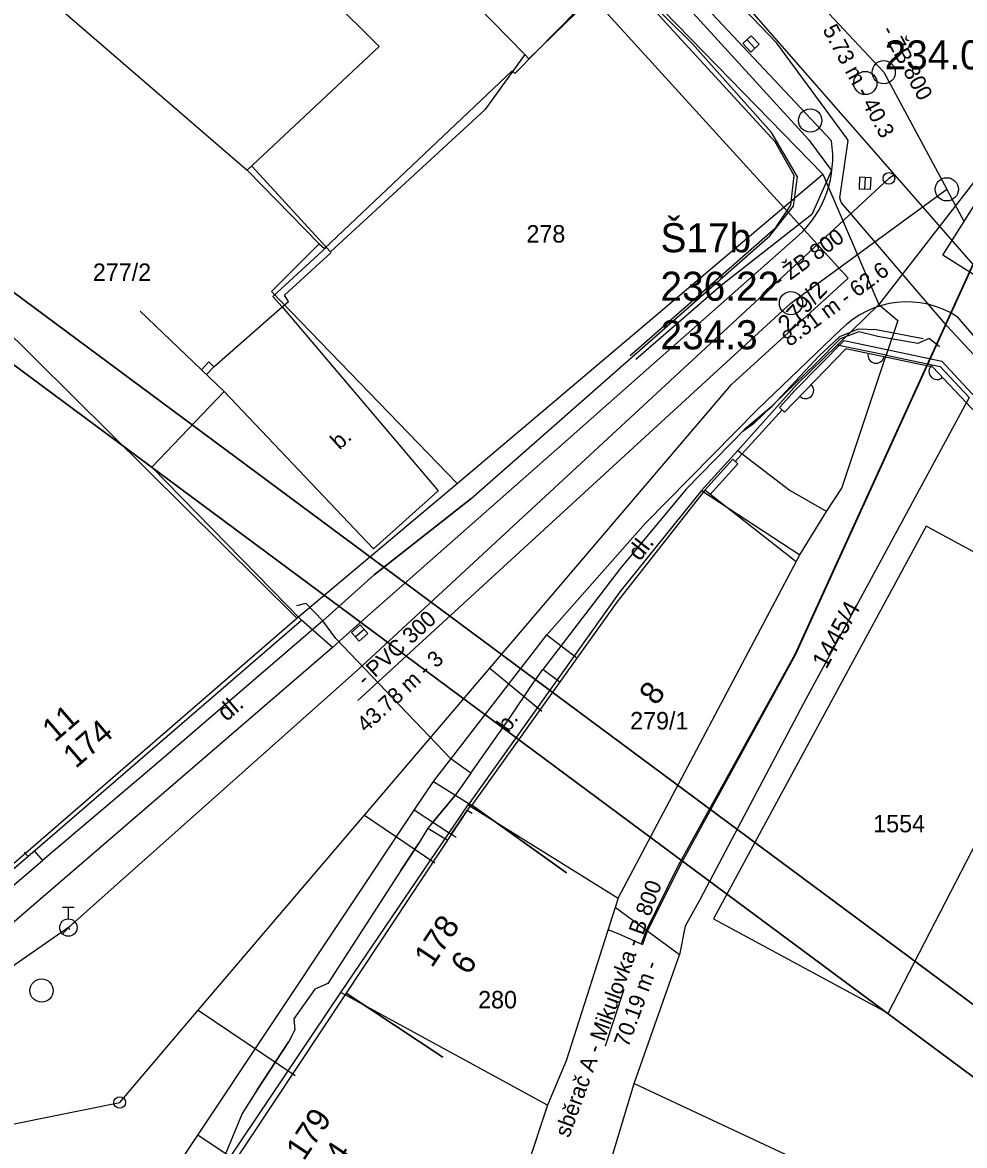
# Model space of a CAD drawing. Extents: x -601580 to 4, y -1204314 to 4.
# Drawn here: x -600436.29 to -600395.73, y -1203947.55 to -1203899.19 of the extents above; entities that cross this region are included whole.
import ezdxf

# ---------------------------------------------------------------- set-up
doc = ezdxf.new("R2010")
doc.units = 0
for name, color, linetype in [('00-EON NN', 7, 'Continuous'), ('00-EON VN', 7, 'Continuous'), ('00-INNOGY-NTL', 7, 'Continuous'), ('00-INNOGY-STL', 7, 'Continuous'), ('00-KN-HRANICE PARCEL', 7, 'Continuous'), ('00-KN-PARC. CISLA', 7, 'Continuous'), ('00-KN-VNITRNI KRESBA', 7, 'Continuous'), ('00-POLOHOPIS', 7, 'Continuous'), ('00-RAZÍTKO', 7, 'Continuous'), ('00-SITE KOM. KABEL', 7, 'Continuous'), ('00-VAK-KANAL-ODLEHCOVACI KOMORA', 7, 'Continuous'), ('00-VAK-KANAL-POPIS', 7, 'Continuous'), ('00-VAK-KANAL-POTRUBI', 7, 'Continuous'), ('00-VAK-VODA-RAD IGIS', 7, 'Continuous'), ('Vrstva 27', 7, 'Continuous'), ('Vrstva 28', 7, 'Continuous'), ('Vrstva 40', 7, 'Continuous'), ('Vrstva 6', 7, 'Continuous')]:
    doc.layers.add(name, color=color, linetype=linetype)

# ---------------------------------------------------------------- blocks, each defined once
blk = doc.blocks.new('6.14A_864')
at = {"layer": 'Vrstva 28'}
blk.add_circle((0, 0), 0.25, dxfattribs=at)
blk = doc.blocks.new('6.13_280')
at = {"layer": 'Vrstva 28'}
for p, q in [((-0.25, 0.875), (0.25, 0.875)), ((0, 0.375), (0, 0.875)), ((-0.258, -0.272), (0.272, 0.258))]:
    blk.add_line(p, q, dxfattribs=at)
blk.add_circle((0, 0), 0.375, dxfattribs=at)
blk = doc.blocks.new('6.30_278')
at = {"layer": 'Vrstva 27'}
blk.add_line((-0.25, 0), (0.25, 0), dxfattribs=at)
blk.add_lwpolyline([(-0.25, -0.249), (0.249, -0.25), (0.25, 0.249), (-0.249, 0.25)], close=True, dxfattribs=at)
blk = doc.blocks.new('6.20_204')
at = {"layer": 'Vrstva 27'}
blk.add_circle((0, 0), 0.5, dxfattribs=at)
blk = doc.blocks.new('6.20_206')
at = {"layer": 'Vrstva 27'}
blk.add_circle((0, 0), 0.5, dxfattribs=at)
blk = doc.blocks.new('6.20_208')
at = {"layer": 'Vrstva 27'}
blk.add_circle((0, 0), 0.5, dxfattribs=at)
blk = doc.blocks.new('6.30_282')
at = {"layer": 'Vrstva 27'}
blk.add_line((-0.25, 0), (0.25, 0), dxfattribs=at)
blk.add_lwpolyline([(-0.25, -0.25), (0.25, -0.25), (0.25, 0.25), (-0.25, 0.25)], close=True, dxfattribs=at)
blk = doc.blocks.new('6.30_284')
at = {"layer": 'Vrstva 27'}
blk.add_line((-0.25, 0.001), (0.25, -0.001), dxfattribs=at)
blk.add_lwpolyline([(-0.25, -0.25), (0.25, -0.25), (0.25, 0.25), (-0.25, 0.25)], close=True, dxfattribs=at)
blk = doc.blocks.new('6.20_210')
at = {"layer": 'Vrstva 27'}
blk.add_circle((0, 0), 0.5, dxfattribs=at)
blk = doc.blocks.new('6.14A_1010')
at = {"layer": 'Vrstva 28'}
blk.add_circle((0, 0), 0.25, dxfattribs=at)
blk = doc.blocks.new('DL_52')
at = {"layer": 'Vrstva 40'}
blk.add_text('dl.', height=0.75, rotation=0, dxfattribs=at).set_placement((-0.174, -0.376))
blk = doc.blocks.new('DL_54')
at = {"layer": 'Vrstva 40'}
blk.add_text('dl.', height=0.75, rotation=0, dxfattribs=at).set_placement((-0.174, -0.375))
blk = doc.blocks.new('VCHOD_1788')
at = {"layer": 'Vrstva 6'}
blk.add_line((0, 0.25), (0, 0), dxfattribs=at)
blk = doc.blocks.new('VCHOD_1790')
at = {"layer": 'Vrstva 6'}
blk.add_line((0, 0.25), (0, 0), dxfattribs=at)
blk = doc.blocks.new('VCHOD_1806')
at = {"layer": 'Vrstva 6'}
blk.add_line((0, 0.25), (0, 0), dxfattribs=at)

msp = doc.modelspace()

# ---------------------------------------------------------------- linework, layer by layer
for points in [[(-600427.929, -1203789.586), (-600429.936, -1203788.096), (-600492.548, -1203872.448), (-600373.307, -1203960.957), (-600310.695, -1203876.605), (-600312.703, -1203875.115)], [(-600429.419, -1203791.594), (-600489.051, -1203871.931), (-600373.825, -1203957.46), (-600314.193, -1203877.122)]]:
    msp.add_lwpolyline(points)
at = {"layer": '00-EON NN'}
for points in [[(-600410.131, -1203913.539), (-600403.86, -1203908.02), (-600403.21, -1203907.06), (-600403.07, -1203905.78), (-600403.89, -1203904.33), (-600408.9, -1203898.88), (-600410.19, -1203896.39), (-600411.3, -1203895.29), (-600423.639, -1203882.179), (-600423.775, -1203882.311), (-600424.137, -1203882.385)], [(-600396.812, -1203913.161), (-600397.26, -1203912.8), (-600397.74, -1203913.02), (-600399.46, -1203912.71), (-600400.29, -1203912.51), (-600401.09, -1203912.81), (-600402.13, -1203913.88), (-600404.82, -1203916.48), (-600405.273, -1203916.806)]]:
    msp.add_lwpolyline(points, dxfattribs=at)
at = {"layer": '00-EON VN'}
msp.add_lwpolyline([(-600433.941, -1203870.22), (-600433.675, -1203870.696), (-600426.744, -1203878.086), (-600409.663, -1203896.312), (-600402.458, -1203904.238), (-600401.465, -1203905.565), (-600402.307, -1203907.459), (-600406.208, -1203910.525), (-600409.879, -1203913.709)], dxfattribs=at)
at = {"layer": '00-INNOGY-NTL'}
for p, q in [((-600416.17, -1203927), (-600413.93, -1203928.84)), ((-600421.56, -1203933.32), (-600418.53, -1203935.38)), ((-600428.72, -1203941.72), (-600424.55, -1203944.53))]:
    msp.add_line(p, q, dxfattribs=at)
for points in [[(-600405.77, -1203914.78), (-600400.75, -1203910.2), (-600411.82, -1203898.02)], [(-600441.937, -1203947.699), (-600438.08, -1203946.9), (-600432.1, -1203945.69), (-600428.72, -1203941.72), (-600421.56, -1203933.32), (-600416.17, -1203927), (-600405.77, -1203914.78)]]:
    msp.add_lwpolyline(points, dxfattribs=at)
at = {"layer": '00-INNOGY-STL'}
msp.add_lwpolyline([(-600376.62, -1203959.39), (-600379.28, -1203942.39), (-600380.4, -1203936.55), (-600380.97, -1203934.27), (-600383.03, -1203928.31), (-600387.74, -1203922.51), (-600393.27, -1203915.72), (-600394.06, -1203914.88), (-600396.47, -1203912.28), (-600396.484, -1203912.264), (-600401.03, -1203906.96), (-600401.08, -1203906.85), (-600401.1, -1203906.75), (-600400.76, -1203904.37), (-600400.74, -1203904.28), (-600400.82, -1203904.16), (-600403.82, -1203900.09), (-600410.79, -1203892.81)], dxfattribs=at)
at = {"layer": '00-KN-HRANICE PARCEL'}
for p, q in [((-600401.83, -1203905.73), (-600410.56, -1203896.77)), ((-600424.48, -1203924.84), (-600448.34, -1203901.22)), ((-600393.75, -1203904.02), (-600399.42, -1203911.34)), ((-600417.58, -1203919.05), (-600401.83, -1203905.73)), ((-600401.83, -1203905.73), (-600399.42, -1203911.34)), ((-600401.22, -1203913.09), (-600399.42, -1203911.34)), ((-600399.42, -1203911.34), (-600398.61, -1203912.03)), ((-600398.61, -1203912.03), (-600399.11, -1203913.52)), ((-600399.11, -1203913.52), (-600401.22, -1203913.09)), ((-600401.01, -1203919.25), (-600399.11, -1203913.52)), ((-600424.48, -1203924.84), (-600417.58, -1203919.05)), ((-600422.58, -1203940.96), (-600417.1, -1203932.87)), ((-600417.1, -1203932.87), (-600410.65, -1203936.89)), ((-600410.65, -1203936.89), (-600410.78, -1203937.3)), ((-600410.78, -1203937.3), (-600412.88, -1203943.9)), ((-600408, -1203939.33), (-600410.78, -1203937.3)), ((-600409.95, -1203944.88), (-600408, -1203939.33)), ((-600413.68, -1203945.81), (-600422.58, -1203940.96)), ((-600412.88, -1203943.9), (-600413.68, -1203945.81)), ((-600414.38, -1203959.53), (-600409.95, -1203944.88)), ((-600413.68, -1203945.81), (-600414.57, -1203948.49))]:
    msp.add_line(p, q, dxfattribs=at)
for points in [[(-600439.16, -1203894.25), (-600435.72, -1203897.69), (-600426.61, -1203905.56), (-600423.51, -1203908.72)], [(-600423.51, -1203908.72), (-600423.28, -1203908.93), (-600415.21, -1203901.28), (-600415.1, -1203901.39), (-600410.56, -1203896.77)], [(-600417.58, -1203919.05), (-600425.57, -1203910.78), (-600423.51, -1203908.72)], [(-600401.22, -1203913.09), (-600402.95, -1203914.78), (-600405.5, -1203917.62), (-600407.05, -1203919.34)], [(-600399.11, -1203913.52), (-600396.78, -1203914), (-600395.53, -1203915.34)], [(-600395.53, -1203915.34), (-600402.66, -1203928.51), (-600407.11, -1203936.94), (-600407.76, -1203938.1), (-600408, -1203939.33)], [(-600407.05, -1203919.34), (-600410.57, -1203923.7), (-600417.1, -1203932.87)], [(-600410.65, -1203936.89), (-600402.83, -1203922.12), (-600401.67, -1203920.25), (-600401.01, -1203919.25)], [(-600399.02, -1203941.85), (-600392.29, -1203928.81), (-600393.66, -1203928.06), (-600391.5, -1203924.07), (-600397.39, -1203920.88), (-600406.54, -1203937.78), (-600399.02, -1203941.85)], [(-600440.54, -1203935.41), (-600438.3, -1203936.79), (-600424.48, -1203924.84)], [(-600433.15, -1203956.7), (-600427.43, -1203948.18), (-600422.58, -1203940.96)], [(-600409.95, -1203944.88), (-600399.63, -1203949.71), (-600397.91, -1203950.4), (-600393.14, -1203953.3), (-600386.83, -1203959.01), (-600378.95, -1203962.27)]]:
    msp.add_lwpolyline(points, dxfattribs=at)
at = {"layer": '00-KN-VNITRNI KRESBA'}
for p, q in [((-600420.94, -1203900.23), (-600429.35, -1203891.83)), ((-600426.61, -1203905.56), (-600420.94, -1203900.23)), ((-600405.5, -1203917.62), (-600403.23, -1203919.36)), ((-600407.05, -1203919.34), (-600402.83, -1203922.12)), ((-600401.67, -1203920.25), (-600403.23, -1203919.36))]:
    msp.add_line(p, q, dxfattribs=at)
at = {"layer": '00-POLOHOPIS'}
for p, q in [((-600409.235, -1203895.995), (-600401.465, -1203904.293)), ((-600402.887, -1203908.372), (-600412.803, -1203917.137)), ((-600423.205, -1203908.875), (-600425.505, -1203910.992)), ((-600423.002, -1203909.096), (-600425.005, -1203910.939)), ((-600425.505, -1203910.992), (-600425.102, -1203911.43)), ((-600425.102, -1203911.43), (-600424.835, -1203911.205)), ((-600424.835, -1203911.205), (-600425.005, -1203910.939)), ((-600428.046, -1203914.013), (-600425.102, -1203911.43)), ((-600428.046, -1203914.013), (-600425.102, -1203911.43)), ((-600425.102, -1203911.43), (-600418.394, -1203919.365)), ((-600396.048, -1203911.865), (-600391.792, -1203916.861)), ((-600404.659, -1203915.868), (-600401.054, -1203912.417)), ((-600400.918, -1203912.893), (-600396.711, -1203913.779)), ((-600400.839, -1203913.239), (-600403.479, -1203915.968)), ((-600397.094, -1203914.028), (-600400.839, -1203913.239)), ((-600428.585, -1203914.145), (-600428.263, -1203913.806)), ((-600428.368, -1203914.352), (-600428.046, -1203914.013)), ((-600428.046, -1203914.013), (-600428.263, -1203913.806)), ((-600395.211, -1203916.047), (-600397.094, -1203914.028)), ((-600394.882, -1203915.74), (-600396.711, -1203913.779)), ((-600421.181, -1203921.861), (-600427.604, -1203915.082)), ((-600409.48, -1203920.768), (-600404.659, -1203915.868)), ((-600405.607, -1203918.089), (-600403.58, -1203915.877)), ((-600403.479, -1203915.968), (-600403.702, -1203915.767)), ((-600412.803, -1203917.137), (-600422.044, -1203925.282)), ((-600405.49, -1203918.194), (-600405.713, -1203917.993)), ((-600418.394, -1203919.365), (-600421.181, -1203921.861)), ((-600413.715, -1203925.556), (-600409.48, -1203920.768)), ((-600422.935, -1203926.11), (-600424.276, -1203924.929)), ((-600422.044, -1203925.282), (-600422.935, -1203926.11)), ((-600418.592, -1203931.877), (-600413.715, -1203925.556)), ((-600413.715, -1203925.556), (-600412.419, -1203926.55)), ((-600422.935, -1203926.11), (-600437.564, -1203938.692)), ((-600419.42, -1203933.107), (-600418.592, -1203931.877)), ((-600418.592, -1203931.877), (-600416.982, -1203932.87)), ((-600416.94, -1203932.898), (-600416.982, -1203932.87)), ((-600428.745, -1203947.103), (-600419.42, -1203933.107)), ((-600417.836, -1203934.157), (-600419.42, -1203933.107)), ((-600417.827, -1203934.144), (-600417.144, -1203933.115)), ((-600436.05, -1203935.107), (-600438.091, -1203936.853)), ((-600430.303, -1203949.446), (-600428.745, -1203947.103)), ((-600427.133, -1203948.173), (-600428.745, -1203947.103))]:
    msp.add_line(p, q, dxfattribs=at)
for points in [[(-600415.57, -1203891.293), (-600410.375, -1203896.735), (-600414.488, -1203900.759), (-600414.662, -1203900.58), (-600418.152, -1203896.999)], [(-600418.152, -1203896.999), (-600414.662, -1203900.58), (-600416.378, -1203902.962), (-600423.022, -1203909.074), (-600426.407, -1203905.394)], [(-600448.815, -1203937.009), (-600445.286, -1203940.551), (-600440.445, -1203935.643), (-600438.697, -1203937.376), (-600424.276, -1203924.929), (-600430.717, -1203918.338), (-600427.604, -1203915.082), (-600431.218, -1203911.627)], [(-600400.918, -1203912.893), (-600403.029, -1203915.022), (-600403.702, -1203915.767)], [(-600400.839, -1203913.239), (-600403.479, -1203915.968)], [(-600397.094, -1203914.028), (-600400.839, -1203913.239)], [(-600395.211, -1203916.047), (-600397.094, -1203914.028)], [(-600405.713, -1203917.993), (-600406.92, -1203919.329)], [(-600405.49, -1203918.194), (-600406.697, -1203919.53)], [(-600402.989, -1203922.419), (-600406.92, -1203919.329), (-600410.708, -1203924.147), (-600416.94, -1203932.898), (-600412.868, -1203935.798)], [(-600412.868, -1203935.798), (-600416.94, -1203932.898), (-600416.982, -1203932.87), (-600422.359, -1203940.98), (-600418.192, -1203943.743)], [(-600418.192, -1203943.743), (-600422.359, -1203940.98), (-600428.673, -1203950.494), (-600424.546, -1203953.276)]]:
    msp.add_lwpolyline(points, dxfattribs=at)
for centre, radius, start, end in [((-600405.95, -1203905.017), 4.543, 312.394, 9.1673), ((-600398.213, -1203915.204), 3.979, 57.0355, 135.5494), ((-600399.54, -1203913.513), 0.35, 168.1029, 348.1029), ((-600396.916, -1203914.219), 0.35, 133.0038, 313.0038), ((-600402.577, -1203915.036), 0.35, 225.9497, 45.9497)]:
    msp.add_arc(centre, radius, start, end, dxfattribs=at)
at = {"layer": '00-RAZÍTKO'}
for points in [[(-600492.548, -1203872.448), (-600304.712, -1203619.391), (-600185.471, -1203707.9), (-600373.307, -1203960.957)], [(-600489.051, -1203871.931), (-600304.195, -1203622.889), (-600188.969, -1203708.417), (-600373.825, -1203957.46)]]:
    msp.add_lwpolyline(points, close=True, dxfattribs=at)
at = {"layer": '00-SITE KOM. KABEL'}
for points in [[(-600423.36, -1203924.95), (-600421.15, -1203922.98), (-600416.99, -1203919.71), (-600404.12, -1203908.38), (-600403.09, -1203907.1), (-600402.93, -1203905.84), (-600404.04, -1203903.93), (-600407.45, -1203900.12), (-600409.62, -1203897.95)], [(-600407.45, -1203900.12), (-600404.04, -1203903.93)], [(-600397.52, -1203912.81), (-600399.54, -1203912.43), (-600400.32, -1203912.4), (-600401.11, -1203912.73), (-600402.01, -1203913.56), (-600404.01, -1203915.72), (-600405.19, -1203916.71), (-600407.72, -1203919.28), (-600410.54, -1203922.69), (-600413.89, -1203927.05)], [(-600405.19, -1203916.71), (-600404.01, -1203915.72), (-600402.01, -1203913.56)], [(-600416.99, -1203919.71), (-600421.15, -1203922.98)], [(-600424.48, -1203924.29), (-600424.09, -1203924.19), (-600423.36, -1203924.95)], [(-600423.36, -1203924.95), (-600430.53, -1203931.13), (-600435.42, -1203935.27)], [(-600416.99, -1203931.51), (-600417.85, -1203930.9), (-600422.8, -1203925.72), (-600423.36, -1203924.95)], [(-600417.85, -1203930.9), (-600422.8, -1203925.72)], [(-600416.99, -1203931.51), (-600415.31, -1203929.13), (-600414.34, -1203927.7), (-600413.89, -1203927.05)], [(-600413.16, -1203927.6), (-600413.89, -1203927.05)], [(-600415.31, -1203929.13), (-600414.34, -1203927.7)], [(-600416.99, -1203931.51), (-600417.68, -1203932.49), (-600418.68, -1203933.7), (-600418.84, -1203933.88)], [(-600418.68, -1203933.7), (-600417.68, -1203932.49)], [(-600418.84, -1203933.88), (-600419.23, -1203934.53), (-600420, -1203935.7), (-600423.15, -1203940.57), (-600423.7, -1203940.81), (-600424.6, -1203942.09), (-600424.57, -1203942.57), (-600424.82, -1203943.06), (-600426.18, -1203945.15), (-600426.83, -1203946.17), (-600427.63, -1203948.12)], [(-600418.84, -1203933.88), (-600418.01, -1203934.39)], [(-600435.79, -1203934.86), (-600435.42, -1203935.27)], [(-600420, -1203935.7), (-600419.23, -1203934.53)], [(-600444.09, -1203939.34), (-600442.92, -1203940.82), (-600438.92, -1203938.24), (-600435.42, -1203935.27)], [(-600426.18, -1203945.15), (-600424.82, -1203943.06)]]:
    msp.add_lwpolyline(points, dxfattribs=at)
at = {"layer": '00-VAK-KANAL-ODLEHCOVACI KOMORA'}
msp.add_lwpolyline([(-600395.19, -1203906.88), (-600391.887, -1203908.941), (-600393.37, -1203911.29), (-600396.663, -1203909.211)], close=True, dxfattribs=at)
at = {"layer": '00-VAK-KANAL-POTRUBI'}
for p, q in [((-600436.153, -1203861.776), (-600399.213, -1203901.336)), ((-600399.213, -1203901.336), (-600396.5, -1203906.377)), ((-600403.206, -1203911.279), (-600396.5, -1203906.377)), ((-600395.751, -1203907.768), (-600396.5, -1203906.377)), ((-600421.848, -1203928.381), (-600403.206, -1203911.279)), ((-600411.086, -1203938.248), (-600410.621, -1203938.425)), ((-600410.621, -1203938.425), (-600409.6, -1203938.884))]:
    msp.add_line(p, q, dxfattribs=at)
for points in [[(-600394.486, -1203908.145), (-600394.519, -1203908.171), (-600394.993, -1203908.754), (-600403.034, -1203926.405), (-600408.072, -1203935.512), (-600409.436, -1203938.281), (-600409.654, -1203938.86)], [(-600394.486, -1203908.145), (-600394.981, -1203908.766), (-600403.004, -1203926.408), (-600408.023, -1203935.561), (-600409.411, -1203938.366), (-600409.585, -1203938.843), (-600409.6, -1203938.884)], [(-600410.395, -1203940.826), (-600410.395, -1203940.826), (-600411.202, -1203943.273), (-600411.202, -1203943.273)]]:
    msp.add_lwpolyline(points, dxfattribs=at)
for centre in [(-600399.213, -1203901.336), (-600396.5, -1203906.377), (-600403.206, -1203911.279)]:
    msp.add_circle(centre, 0.5, dxfattribs=at)
at = {"layer": '00-VAK-VODA-RAD IGIS'}
for points in [[(-600435.585, -1203867.866), (-600433.489, -1203869.554), (-600422.424, -1203879.956), (-600409.57, -1203893.38), (-600398.755, -1203905.752)], [(-600398.99, -1203905.908), (-600421.855, -1203927.068), (-600434.311, -1203938.16)], [(-600398.755, -1203905.752), (-600398.99, -1203905.908)], [(-600398.755, -1203905.752), (-600392.081, -1203913.383)], [(-600434.311, -1203938.16), (-600451.544, -1203950.135), (-600457.931, -1203948.021)], [(-600434.311, -1203938.16), (-600434.261, -1203938.238)]]:
    msp.add_lwpolyline(points, dxfattribs=at)

# ---------------------------------------------------------------- block references
at = {"layer": '00-POLOHOPIS'}
for name, p, xscale, yscale, rotation in [('6.30_278', (-600404.925, -1203900.118), 1.00000095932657, 1.0000009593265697, -46.88202572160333), ('6.20_204', (-600400.005, -1203901.802), 0.99999888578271, 0.9999988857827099, 87.47948054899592), ('6.20_206', (-600402.378, -1203903.414), 0.99999888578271, 0.9999988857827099, 87.47948054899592), ('6.30_282', (-600400.013, -1203906.116), 0.9999997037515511, 0.999999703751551, 87.12690925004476), ('6.20_208', (-600403.206, -1203911.279), 0.99999888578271, 0.9999988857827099, 87.47948054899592), ('DL_54', (-600409.902, -1203922.052), 1.00000150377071, 1.00000150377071, 51.82483609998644), ('6.30_284', (-600421.772, -1203925.475), 1.00000016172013, 1.00000016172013, 41.39309171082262), ('DL_52', (-600427.617, -1203928.918), 0.9999994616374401, 0.99999946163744, 40.79799375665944), ('VCHOD_1790', (-600417.144, -1203933.115), 1.0000008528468, 1.0000008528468, -123.57411218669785), ('VCHOD_1788', (-600417.827, -1203934.144), 1.0000008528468, 1.0000008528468, -123.57411218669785), ('VCHOD_1806', (-600436.05, -1203935.107), 0.99999908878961, 0.9999990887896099, 40.54578951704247), ('6.20_210', (-600435.465, -1203940.874), 1.00000016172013, 1.00000016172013, 41.39309171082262), ('6.14A_1010', (-600432.104, -1203945.693), 1.00000054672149, 1.00000054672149, 40.69792207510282)]:
    msp.add_blockref(name, p, dxfattribs=dict(at, xscale=xscale, yscale=yscale, rotation=rotation))
for name, p in [('6.14A_864', (-600398.99, -1203905.908)), ('6.13_280', (-600434.311, -1203938.16))]:
    msp.add_blockref(name, p, dxfattribs=at)

# ---------------------------------------------------------------- texts
at = {"layer": '00-KN-PARC. CISLA'}
for s, p in [('278', (-600414.594, -1203908.67)), ('277/2', (-600433.26, -1203910.32)), ('279/1', (-600410.129, -1203929.63)), ('1554', (-600399.665, -1203934.06)), ('280', (-600416.674, -1203941.64))]:
    msp.add_text(s, height=0.75, dxfattribs=at).set_placement(p)
for s, rotation, p in [('279/2', 47, (-600403.306, -1203912.584)), ('1445/4', 61, (-600401.683, -1203927.064))]:
    msp.add_text(s, height=0.75, rotation=rotation, dxfattribs=at).set_placement(p)
at = {"layer": '00-POLOHOPIS'}
for s, height, rotation, p in [('b.', 0.7, 41.8472, (-600422.645, -1203917.619)), ('8', 1, 54.541, (-600409.001, -1203928.646)), ('11', 1, 40.798, (-600434.896, -1203930.213)), ('b.', 0.7, 54.5435, (-600415.362, -1203929.789)), ('174', 1, 40.798, (-600433.999, -1203931.34)), ('178', 1, 56.4553, (-600418.662, -1203939.929)), ('6', 1, 56.4553, (-600417.091, -1203940.252)), ('179', 1, 56.4296, (-600424.179, -1203948.242)), ('4', 1, 56.4296, (-600422.512, -1203948.443))]:
    msp.add_text(s, height=height, rotation=rotation, dxfattribs=at).set_placement(p)
at = {"layer": '00-VAK-KANAL-POPIS'}
for s, height, rotation, p in [('5.73 m - 40.3', 0.68241, 298.2888, (-600401.861, -1203899.502)), ('- ŽB 800', 0.6824, 298.2888, (-600399.33, -1203899.537)), ('- ŽB 800', 0.6824, 36.1638, (-600403.68, -1203910.636)), ('8.31 m - 62.6', 0.68241, 36.1638, (-600403.268, -1203913.175)), ('- PVC 300', 0.6824, 42.5338, (-600421.527, -1203927.804)), ('43.78 m - 3', 0.68241, 42.5338, (-600421.508, -1203929.796)), ('sběrač A - Mikulovka - B 800', 0.68241, 69.918, (-600412.759, -1203947.241)), ('70.19 m -', 0.6824, 69.918, (-600410.215, -1203943.354))]:
    msp.add_text(s, height=height, rotation=rotation, dxfattribs=at).set_placement(p)
for s, p in [('234.01', (-600399.177, -1203901.214)), ('Š17b', (-600408.823, -1203909.087)), ('236.22', (-600408.823, -1203911.175)), ('234.3', (-600408.823, -1203913.263))]:
    msp.add_text(s, height=1.25, dxfattribs=at).set_placement(p)

doc.saveas('drawing.dxf')
